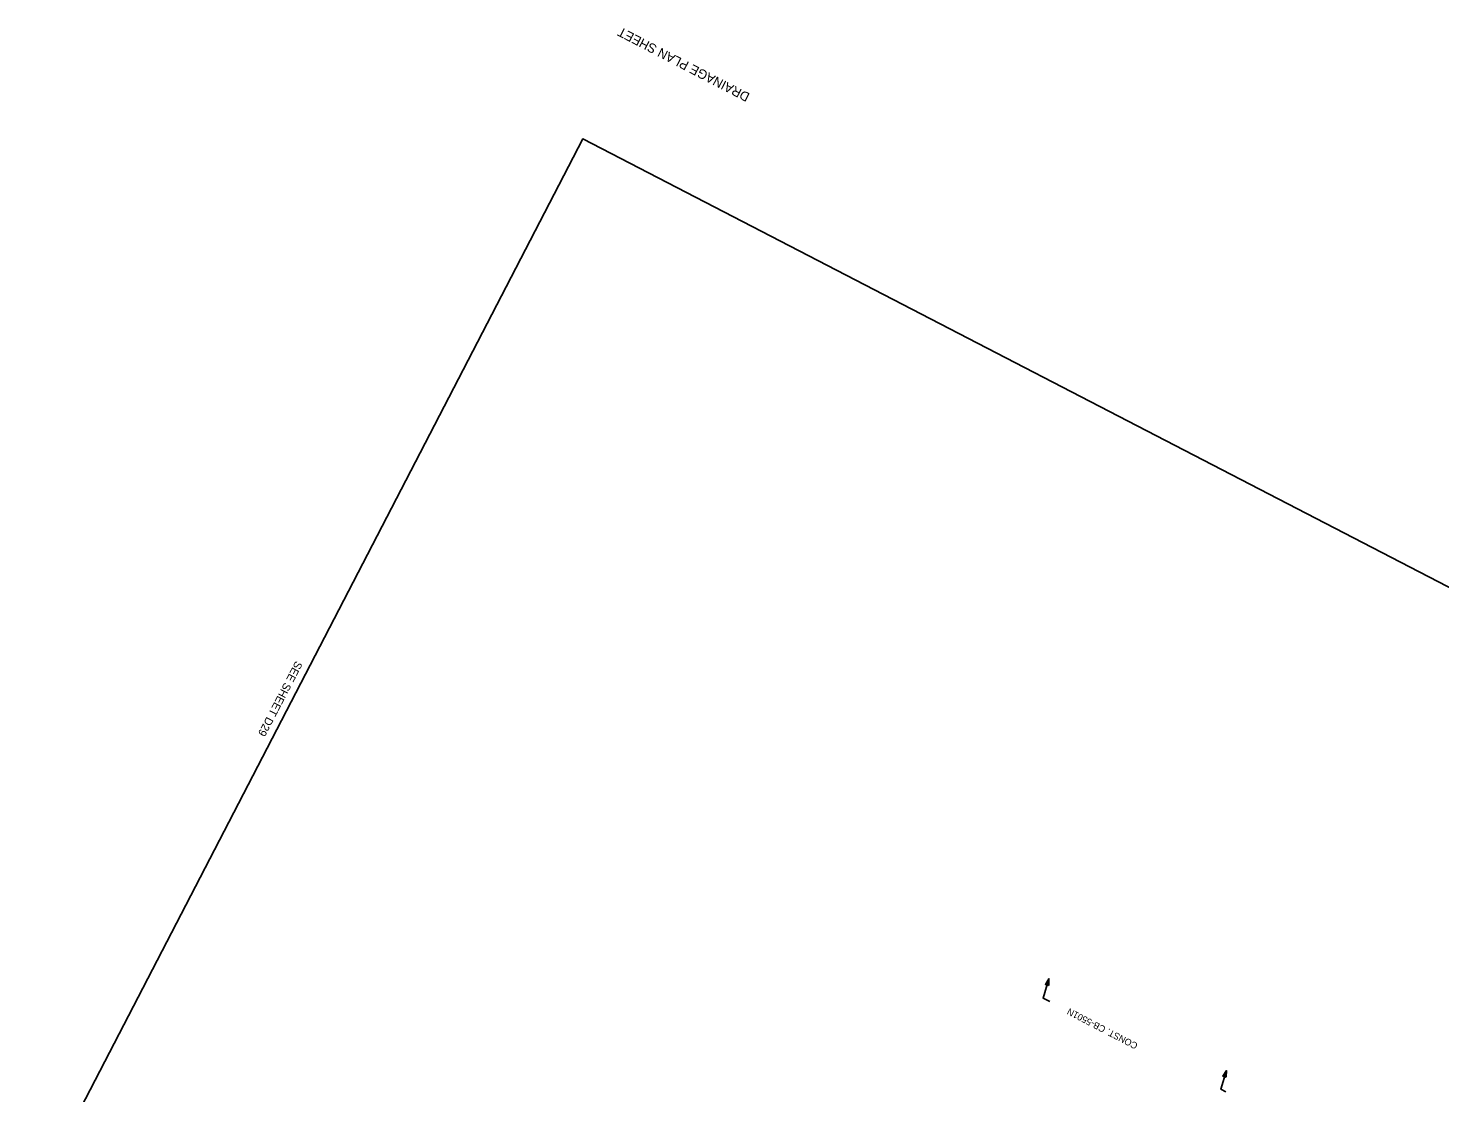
# Model space of a CAD drawing. Extents: x 1606408 to 1608529, y 1094514 to 1096115.
# Drawn here: x 1606468 to 1607526, y 1095316 to 1096115 of the extents above; entities that cross this region are included whole.
import ezdxf

# ---------------------------------------------------------------- set-up
doc = ezdxf.new("R2010")
doc.units = 0
for name, color, linetype in [('RD_HC_TX_Sta50', 7, 'Continuous'), ('RD_HY_Area_SS1', 7, 'Continuous'), ('RD_Sketch9', 7, 'Continuous'), ('RD_TX_Drainage', 7, 'Continuous')]:
    doc.layers.add(name, color=color, linetype=linetype)

msp = doc.modelspace()

# ---------------------------------------------------------------- linework, layer by layer
at = {"layer": 'RD_HC_TX_Sta50'}
msp.add_lwpolyline([(1607787.2, 1094514.3), (1606590.9, 1095133.7), (1606603.3, 1095157.8), (1606468, 1095228.7), (1606883.8, 1096031.8), (1608215.8, 1095342.1)], close=True, dxfattribs=at)
msp.add_lwpolyline([(1607787.2, 1094514.3), (1606590.9, 1095133.7), (1606603.3, 1095157.8), (1606468, 1095228.7), (1606883.8, 1096031.8), (1608215.8, 1095342.1)], close=True, dxfattribs=at)
msp.add_lwpolyline([(1607787.2, 1094514.3), (1606590.9, 1095133.7), (1606603.3, 1095157.8), (1606468, 1095228.7), (1606883.8, 1096031.8), (1608215.8, 1095342.1)], close=True, dxfattribs=at)
msp.add_lwpolyline([(1607787.2, 1094514.3), (1606590.9, 1095133.7), (1606603.3, 1095157.8), (1606468, 1095228.7), (1606883.8, 1096031.8), (1608215.8, 1095342.1)], close=True, dxfattribs=at)
msp.add_lwpolyline([(1607787.2, 1094514.3), (1606590.9, 1095133.7), (1606603.3, 1095157.8), (1606468, 1095228.7), (1606883.8, 1096031.8), (1608215.8, 1095342.1)], close=True, dxfattribs=at)
msp.add_lwpolyline([(1607787.2, 1094514.3), (1606590.9, 1095133.7), (1606603.3, 1095157.8), (1606468, 1095228.7), (1606883.8, 1096031.8), (1608215.8, 1095342.1)], close=True, dxfattribs=at)
at = {"layer": 'RD_Sketch9'}
for points in [[(1607233.9, 1095384.8), (1607228.9, 1095387.3), (1607233.3, 1095401.8)], [(1607366, 1095317), (1607362.1, 1095319.1), (1607366.5, 1095332.9)]]:
    msp.add_lwpolyline(points, dxfattribs=at)
for points in [[(1607233.1, 1095396.8), (1607233.3, 1095401.8), (1607230.7, 1095397.6)], [(1607366.2, 1095327.9), (1607366.5, 1095332.9), (1607363.8, 1095328.7)]]:
    msp.add_lwpolyline(points, close=True, dxfattribs=at)

# ---------------------------------------------------------------- texts
at = {"layer": 'RD_HY_Area_SS1'}
msp.add_text('SEE SHEET D29', height=6, rotation=242.5719, dxfattribs=at).set_placement((1606668.6, 1095640.7))
at = {"layer": 'RD_Sketch9'}
msp.add_text('CONST. CB-5501N', height=5, rotation=152.6268, dxfattribs=at).set_placement((1607300.4, 1095353.1))
at = {"layer": 'RD_TX_Drainage'}
msp.add_text('DRAINAGE PLAN SHEET', height=6.983, rotation=152.6268, dxfattribs=at).set_placement((1607009.6, 1096065.6))

doc.saveas('drawing.dxf')
